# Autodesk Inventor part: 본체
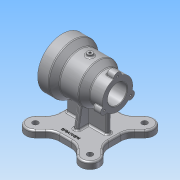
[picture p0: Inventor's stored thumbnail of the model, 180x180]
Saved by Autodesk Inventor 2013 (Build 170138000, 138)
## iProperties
Created: 2017-03
Part Number: 본체
Material: 알루미늄 6061
Document SubType Name: Modeling
Designer: Administrator
Density: 2.71 g/cm^3
Mass: 1005.19 g
Surface Area: 839.933 cm^2
Volume: 370.92 cm^3
Author: Administrator
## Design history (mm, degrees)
sketch "스케치1"
  geometry: L1 (-48, 0)-(52, 0); L2 (52, 0)-(52, 27.5); L3 (52, 27.5)-(29, 27.5); L4 (29, 27.5)-(17, 36); L5 (17, 36)-(-17, 36); L6 (-17, 36)-(-28, 45); L7 (-28, 45)-(-48, 45); L8 (-48, 45)-(-48, 0); 2 further points
  constraints: 16 end point, 3 parallel, 2 perpendicular, 1 horizontal, 1 midpoint, 1 point on line, 1 vertical alignment
  dimensions: "d9" = 55 diameter of L3 L1; "d11" = 72 diameter of L5 L1; "d12" = 90 diameter of L7 L1; "d14" = 23 distance of L2.end L3.end; "d15" = 100 distance between parallel lines of L2 L8; "d16" = 20 distance of L6.end L7.end; "d17" = 31 distance from line of L5.end L8; "d18" = 65 distance from line of L4.end L8
revolve "회전1" sketch "스케치1" stored, may be unused: angle "d19" = 90 deg
hole "구멍1" diameter "d22" = 52; stored, may be unused: countersink angle "d26" = 90 deg, drill point angle "d28" = 0 deg; dims "d20" = 10, "d21" = 10, "d23" = 6, "d24" = 70, "d25" = 23, "d27" = 70
hole "구멍2" diameter "d31" = 35; stored, may be unused: countersink angle "d35" = 90 deg, drill point angle "d37" = 0 deg; dims "d29" = 10, "d30" = 10, "d32" = 6, "d33" = 70, "d34" = 23, "d36" = 30
chamfer "모따기1" distance "d38" = 1; stored, may be unused: second distance "d39" = 2, angle "d40" = 45 deg
fillet "모깎기1" dims "d41" = 3
fillet "모깎기2" dims "d42" = 3
node "작업 평면1"
node "작업 평면3"
sketch "스케치11"
  geometry: L1 (-18.958, 45)-(22.958, 45); L2 (22.958, 45)-(39.477, 61.518); L3 (63.518, 37.477)-(47, 20.958); L4 (47, 20.958)-(47, -20.958); L5 (47, -20.958)-(63.518, -37.477); L6 (39.477, -61.518)-(22.958, -45); L7 (22.958, -45)-(-18.958, -45); L8 (-18.958, -45)-(-35.477, -61.518); L9 (-59.518, -37.477)-(-43, -20.958); L10 (-43, -20.958)-(-43, 20.958); L11 (-43, 20.958)-(-59.518, 37.477); L12 (-35.477, 61.518)-(-18.958, 45); L13 (0, 0)-(2, 0); L14 (2, 0)-(-47.497, 49.497); L15 (2, 0)-(51.497, 49.497); L16 (2, 0)-(-47.497, -49.497); L17 (2, 0)-(51.497, -49.497); A1 r 17 centre (51.497, 49.497) between (63.518, 37.477) and (39.477, 61.518); A2 r 17 centre (51.497, -49.497) between (39.477, -61.518) and (63.518, -37.477); A3 r 17 centre (-47.497, -49.497) between (-59.518, -37.477) and (-35.477, -61.518); A4 r 17 centre (-47.497, 49.497) between (-35.477, 61.518) and (-59.518, 37.477); 2 further points
  constraints: 34 end point, 8 point on circle, 8 tangent, 5 equal length, 5 perpendicular, 4 centre point, 2 equal radius, 2 parallel, 1 coincident, 1 horizontal, 1 midpoint, 1 vertical alignment
  dimensions: "d179" = 2 distance of L13.start L13.end; "d182" = 17 radius of A1; "d183" = 90 distance between parallel lines of L7 L1; "d184" = 45 distance from line of L13.end L7; "d185" = 90 distance between parallel lines of L4 L10; "d186" = 45 distance from line of L13.end L10; "d187" = 70 distance of L13.end L14.end; "d188" = 70 distance of L13.end L15.end; "d189" = 90 deg angle of L15 L14; "d191" = 70 distance of L13.end L16.end; "d192" = 70 distance of L13.end L17.end; "d193" = 90 deg angle of L15 L17; "d194" = 90 deg angle of L16 L17; "d195" = 34 distance between parallel lines of L9 L8
extrude "돌출6" join sketch "스케치11" distance "d196" = 12; taper "d197" = 0 deg
sketch "스케치3"
  geometry: C1 r 5 at (-47.497, -49.497); C2 r 5 at (51.497, -49.497); C3 r 5 at (51.497, 49.497); C4 r 5 at (-47.497, 49.497); A1 r 17 centre (-47.497, -49.497) between (-59.518, -37.477) and (-35.477, -61.518) reference; A2 r 17 centre (51.497, -49.497) between (39.477, -61.518) and (63.518, -37.477) reference; A3 r 17 centre (51.497, 49.497) between (63.518, 37.477) and (39.477, 61.518) reference; A4 r 17 centre (-47.497, 49.497) between (-35.477, 61.518) and (-59.518, 37.477) reference; 1 further point
  constraints: 4 centre point, 4 coincident, 1 equal radius
  dimensions: "d72" = 10 diameter of C1; "d198" = 10 diameter of C3; "d199" = 10 diameter of C4
extrude "돌출2" cut sketch "스케치3" distance "d74" = 12; taper "d75" = 0 deg
fillet "모깎기11" dims "d200" = 25
fillet "모깎기12" dims "d201" = 3
sketch "스케치12"
  geometry: L1 (-37, 4)-(37, 4); L2 (37, 4)-(37, -4); L3 (37, -4)-(-37, -4); L4 (-37, -4)-(-37, 4); 1 further point
  constraints: 8 end point, 2 parallel, 1 horizontal, 1 perpendicular
  dimensions: "d202" = 8 distance of L1.end L2.end; "d204" = 74 distance of L2.end L3.end; "d205" = 37 distance from line of point (0, 0) L2; "d206" = 4 distance from line of point (0, 0) L1
extrude "돌출7" join sketch "스케치12" stored distance "d207" = 12; taper "d208" = 0 deg
sketch "스케치5"
  geometry: L1 (-42, -70)-(-4, -70) reference; L2 (-4, -70)-(-4, -35.777) reference; L3 (4, -35.777)-(4, -70) reference; L4 (4, -70)-(42, -70) reference; L5 (45, -73)-(45, -82) reference; L6 (45, -82)-(-45, -82) reference; L7 (-45, -82)-(-45, -73) reference; L8 (25, -70)-(21.049, -47.594); L9 (-25, -70)-(-21.026, -47.463); C1 r 26 at (0, 0) reference; A1 r 3 centre (-42, -73) between (-42, -70) and (-45, -73) reference; A2 r 36 centre (0, 0) between (4, -35.777) and (-4, -35.777) reference; A3 r 3 centre (42, -73) between (45, -73) and (42, -70) reference
  constraints: 4 end point, 2 point on line
  dimensions: "d209" = 25 horizontal distance of A2.centre L8.start; "d210" = 25 horizontal distance of A2.centre L9.start; "d211" = 100 deg angle of L4 L8; "d212" = 100 deg angle of L1 L9
  node "절단 모서리 투영2"
feature "리브3" dims "d213" = 1, "d214" = 8, "d215" = 0, "d216" = 0, "d217" = 1, "d218" = 1
feature "리브4" dims "d219" = 1, "d220" = 8, "d221" = 0, "d222" = 0, "d223" = 1, "d224" = 1
fillet "모깎기13" dims "d225" = 3
fillet "모깎기14" dims "d226" = 3
sketch "스케치6"
  geometry: A1 r 27.5 centre (0, 0) between (-27.5, 0) and (-26.609, -6.943) reference; A2 r 7 centre (-27.5, 0) between (-26.609, 6.943) and (-26.609, -6.943)
  constraints: 5 point on circle, 1 centre point, 1 horizontal alignment
  dimensions: "d104" = 7 radius of A2
extrude "돌출4" join sketch "스케치6" distance "d106" = 15; taper "d107" = 0 deg
sketch "스케치7"
  geometry: A1 r 7 centre (0, 0) between (0.891, 6.943) and (0.891, -6.943) reference; 1 further point
  constraints: 1 coincident
hole "구멍3" sketch "스케치7" at (0, 0) diameter "d108" = 3.242; stored, may be unused: countersink angle "d112" = 90 deg, drill point angle "d114" = 118 deg; dims "d109" = 9, "d110" = 70, "d111" = 23, "d113" = 11
fillet "모깎기8" dims "d116" = 3
fillet "모깎기7" dims "d115" = 1
sketch "스케치8"
  geometry: C1 r 45 at (0, 0) reference; 1 further point
  constraints: 1 horizontal alignment
  dimensions: "d120" = 40 distance of C1.centre point (40, 0)
hole "구멍4" sketch "스케치8" at (40, 0) diameter "d121" = 3.242; stored, may be unused: countersink angle "d125" = 90 deg, drill point angle "d127" = 118 deg; dims "d122" = 9, "d123" = 70, "d124" = 23, "d126" = 11
node "작업 평면2"
sketch "스케치9"
  geometry: L1 (-48, -45)-(-48, 45) reference; C1 r 5 at (2, 0); 1 further point
  constraints: 1 centre point, 1 horizontal alignment
  dimensions: "d152" = 50 distance from line of L1 C1.centre; "d153" = 10 diameter of C1
extrude "돌출5" join sketch "스케치9" stored distance "d134" = 15; taper "d135" = 0 deg
hole "구멍6" diameter "d156" = 4.134; stored, may be unused: countersink angle "d160" = 90 deg, drill point angle "d162" = 0 deg; dims "d154" = 10, "d155" = 10, "d157" = 9, "d158" = 70, "d159" = 23, "d161" = 20
fillet "모깎기10" dims "d163" = 3
sketch "스케치13"
  geometry: L1 (47, -10.603)-(47, 10.603) reference; 2 further points
  constraints: 1 other
  dimensions: "d227" = 35 vertical distance of point (0, 0) point (2, -35); "d228" = 45 distance from line of L1 point (2, -35)
feature "엠보싱2" sketch "스케치13" dims "d38" = 1, "d229" = 0.5, "d230" = 0
node "솔리드1"
pattern_circular "원형 패턴1" dims "d118" = 360 deg
pattern_circular "원형 패턴2" dims angle "d129" = 360 deg
other parameters: "d43" = -82, "d50" = 17, "d57" = 17, "d62" = 17, "d64" = 17, "d178" = -82
